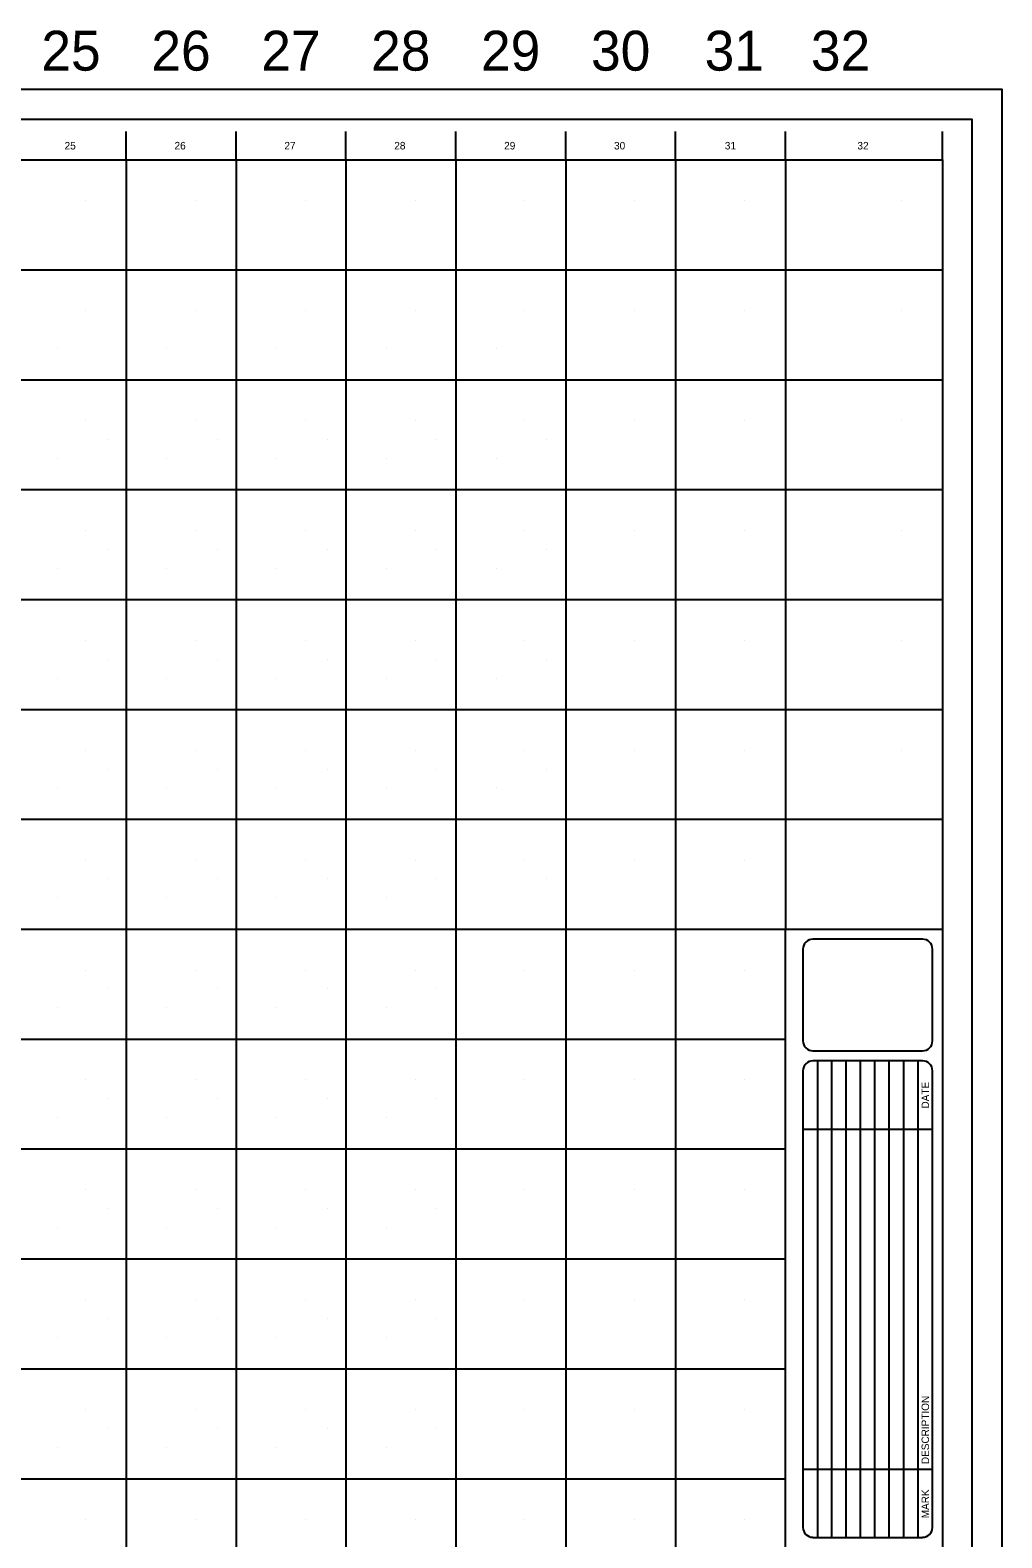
# Model space of a CAD drawing. Extents: x -0.05 to 1.19, y 0 to 0.86.
# Drawn here: x 0.8795 to 1.189, y 0.3796 to 0.8598 of the extents above; entities that cross this region are included whole.
import ezdxf

# ---------------------------------------------------------------- set-up
doc = ezdxf.new("R2010")
doc.units = 0
for name, color, linetype in [('G-ANNO-NPLT', 7, 'Continuous'), ('G-ANNO-TEXT', 7, 'Continuous'), ('G-ANNO-TTLB', 7, 'Continuous'), ('G-ANNO-TTLB-GRID', 7, 'Continuous')]:
    doc.layers.add(name, color=color, linetype=linetype)

msp = doc.modelspace()

# ---------------------------------------------------------------- linework, layer by layer
at = {"layer": 'G-ANNO-NPLT'}
for p, q in [((0.89707, 0.80547), (0.89707, 0.80547)), ((0.93207, 0.80547), (0.93207, 0.80547)), ((0.96707, 0.80547), (0.96707, 0.80547)), ((1.00208, 0.80547), (1.00208, 0.80547)), ((1.03707, 0.80547), (1.03707, 0.80547)), ((1.07207, 0.80547), (1.07207, 0.80547)), ((1.10708, 0.80547), (1.10708, 0.80547)), ((1.15709, 0.80547), (1.15709, 0.80547)), ((0.89707, 0.77047), (0.89707, 0.77047)), ((0.93207, 0.77047), (0.93207, 0.77047)), ((0.96707, 0.77047), (0.96707, 0.77047)), ((1.00208, 0.77047), (1.00208, 0.77047)), ((1.03707, 0.77047), (1.03707, 0.77047)), ((1.07207, 0.77047), (1.07207, 0.77047)), ((1.10708, 0.77047), (1.10708, 0.77047)), ((1.15709, 0.77047), (1.15709, 0.77047)), ((0.88807, 0.75847), (0.88807, 0.75847)), ((0.92307, 0.75847), (0.92307, 0.75847)), ((0.95808, 0.75847), (0.95808, 0.75847)), ((0.99307, 0.75847), (0.99307, 0.75847)), ((1.02807, 0.75847), (1.02807, 0.75847)), ((0.89707, 0.73547), (0.89707, 0.73547)), ((0.93207, 0.73547), (0.93207, 0.73547)), ((0.96707, 0.73547), (0.96707, 0.73547)), ((1.00208, 0.73547), (1.00208, 0.73547)), ((1.03707, 0.73547), (1.03707, 0.73547)), ((1.07207, 0.73547), (1.07207, 0.73547)), ((1.10708, 0.73547), (1.10708, 0.73547)), ((1.15709, 0.73547), (1.15709, 0.73547)), ((0.90407, 0.72947), (0.90407, 0.72947)), ((0.93907, 0.72947), (0.93907, 0.72947)), ((0.97407, 0.72947), (0.97407, 0.72947)), ((1.00907, 0.72947), (1.00907, 0.72947)), ((1.04408, 0.72947), (1.04408, 0.72947)), ((0.88807, 0.72347), (0.88807, 0.72347)), ((0.92307, 0.72347), (0.92307, 0.72347)), ((0.95808, 0.72347), (0.95808, 0.72347)), ((0.99307, 0.72347), (0.99307, 0.72347)), ((1.02807, 0.72347), (1.02807, 0.72347)), ((0.89707, 0.70047), (0.89707, 0.70047)), ((0.93207, 0.70047), (0.93207, 0.70047)), ((0.96707, 0.70047), (0.96707, 0.70047)), ((1.00208, 0.70047), (1.00208, 0.70047)), ((1.03707, 0.70047), (1.03707, 0.70047)), ((1.07207, 0.70047), (1.07207, 0.70047)), ((1.10708, 0.70047), (1.10708, 0.70047)), ((1.15709, 0.70047), (1.15709, 0.70047)), ((0.90407, 0.69447), (0.90407, 0.69447)), ((0.93907, 0.69447), (0.93907, 0.69447)), ((0.97407, 0.69447), (0.97407, 0.69447)), ((1.00907, 0.69447), (1.00907, 0.69447)), ((1.04408, 0.69447), (1.04408, 0.69447)), ((0.88807, 0.68847), (0.88807, 0.68847)), ((0.92307, 0.68847), (0.92307, 0.68847)), ((0.95808, 0.68847), (0.95808, 0.68847)), ((0.99307, 0.68847), (0.99307, 0.68847)), ((1.02807, 0.68847), (1.02807, 0.68847)), ((0.89707, 0.66547), (0.89707, 0.66547)), ((0.93207, 0.66547), (0.93207, 0.66547)), ((0.96707, 0.66547), (0.96707, 0.66547)), ((1.00208, 0.66547), (1.00208, 0.66547)), ((1.03707, 0.66547), (1.03707, 0.66547)), ((1.07207, 0.66547), (1.07207, 0.66547)), ((1.10708, 0.66547), (1.10708, 0.66547)), ((1.15709, 0.66547), (1.15709, 0.66547)), ((0.90407, 0.65947), (0.90407, 0.65947)), ((0.93907, 0.65947), (0.93907, 0.65947)), ((0.97407, 0.65947), (0.97407, 0.65947)), ((1.00907, 0.65947), (1.00907, 0.65947)), ((1.04408, 0.65947), (1.04408, 0.65947)), ((0.88807, 0.65347), (0.88807, 0.65347)), ((0.92307, 0.65347), (0.92307, 0.65347)), ((0.95808, 0.65347), (0.95808, 0.65347)), ((0.99307, 0.65347), (0.99307, 0.65347)), ((1.02807, 0.65347), (1.02807, 0.65347)), ((0.89707, 0.63047), (0.89707, 0.63047)), ((0.93207, 0.63047), (0.93207, 0.63047)), ((0.96707, 0.63047), (0.96707, 0.63047)), ((1.00208, 0.63047), (1.00208, 0.63047)), ((1.03707, 0.63047), (1.03707, 0.63047)), ((1.07207, 0.63047), (1.07207, 0.63047)), ((1.10708, 0.63047), (1.10708, 0.63047)), ((1.15709, 0.63047), (1.15709, 0.63047)), ((0.90407, 0.62447), (0.90407, 0.62447)), ((0.93907, 0.62447), (0.93907, 0.62447)), ((0.97407, 0.62447), (0.97407, 0.62447)), ((1.00907, 0.62447), (1.00907, 0.62447)), ((1.04408, 0.62447), (1.04408, 0.62447)), ((0.88807, 0.61847), (0.88807, 0.61847)), ((0.92307, 0.61847), (0.92307, 0.61847)), ((0.95808, 0.61847), (0.95808, 0.61847)), ((0.99307, 0.61847), (0.99307, 0.61847)), ((1.02807, 0.61847), (1.02807, 0.61847)), ((0.89707, 0.59547), (0.89707, 0.59547)), ((0.93207, 0.59547), (0.93207, 0.59547)), ((0.96707, 0.59547), (0.96707, 0.59547)), ((1.00208, 0.59547), (1.00208, 0.59547)), ((1.03707, 0.59547), (1.03707, 0.59547)), ((1.07207, 0.59547), (1.07207, 0.59547)), ((1.10708, 0.59547), (1.10708, 0.59547)), ((0.90407, 0.58947), (0.90407, 0.58947)), ((0.93907, 0.58947), (0.93907, 0.58947)), ((0.97407, 0.58947), (0.97407, 0.58947)), ((1.00907, 0.58947), (1.00907, 0.58947)), ((1.04408, 0.58947), (1.04408, 0.58947)), ((0.88807, 0.58347), (0.88807, 0.58347)), ((0.92307, 0.58347), (0.92307, 0.58347)), ((0.95808, 0.58347), (0.95808, 0.58347)), ((0.99307, 0.58347), (0.99307, 0.58347)), ((0.89707, 0.56047), (0.89707, 0.56047)), ((0.93207, 0.56047), (0.93207, 0.56047)), ((0.96707, 0.56047), (0.96707, 0.56047)), ((1.00208, 0.56047), (1.00208, 0.56047)), ((1.03707, 0.56047), (1.03707, 0.56047)), ((1.07207, 0.56047), (1.07207, 0.56047)), ((1.10708, 0.56047), (1.10708, 0.56047)), ((0.90407, 0.55447), (0.90407, 0.55447)), ((0.93907, 0.55447), (0.93907, 0.55447)), ((0.97407, 0.55447), (0.97407, 0.55447)), ((1.00907, 0.55447), (1.00907, 0.55447)), ((0.88807, 0.54847), (0.88807, 0.54847)), ((0.92307, 0.54847), (0.92307, 0.54847)), ((0.95808, 0.54847), (0.95808, 0.54847)), ((0.99307, 0.54847), (0.99307, 0.54847)), ((0.89707, 0.52547), (0.89707, 0.52547)), ((0.93207, 0.52547), (0.93207, 0.52547)), ((0.96707, 0.52547), (0.96707, 0.52547)), ((1.00208, 0.52547), (1.00208, 0.52547)), ((1.03707, 0.52547), (1.03707, 0.52547)), ((1.07207, 0.52547), (1.07207, 0.52547)), ((1.10708, 0.52547), (1.10708, 0.52547)), ((0.90407, 0.51947), (0.90407, 0.51947)), ((0.93907, 0.51947), (0.93907, 0.51947)), ((0.97407, 0.51947), (0.97407, 0.51947)), ((1.00907, 0.51947), (1.00907, 0.51947)), ((0.88807, 0.51347), (0.88807, 0.51347)), ((0.92307, 0.51347), (0.92307, 0.51347)), ((0.95808, 0.51347), (0.95808, 0.51347)), ((0.99307, 0.51347), (0.99307, 0.51347)), ((0.89707, 0.49047), (0.89707, 0.49047)), ((0.93207, 0.49047), (0.93207, 0.49047)), ((0.96707, 0.49047), (0.96707, 0.49047)), ((1.00208, 0.49047), (1.00208, 0.49047)), ((1.03707, 0.49047), (1.03707, 0.49047)), ((1.07207, 0.49047), (1.07207, 0.49047)), ((1.10708, 0.49047), (1.10708, 0.49047)), ((0.90407, 0.48447), (0.90407, 0.48447)), ((0.93907, 0.48447), (0.93907, 0.48447)), ((0.97407, 0.48447), (0.97407, 0.48447)), ((1.00907, 0.48447), (1.00907, 0.48447)), ((0.88807, 0.47847), (0.88807, 0.47847)), ((0.92307, 0.47847), (0.92307, 0.47847)), ((0.95808, 0.47847), (0.95808, 0.47847)), ((0.99307, 0.47847), (0.99307, 0.47847)), ((0.89707, 0.45547), (0.89707, 0.45547)), ((0.93207, 0.45547), (0.93207, 0.45547)), ((0.96707, 0.45547), (0.96707, 0.45547)), ((1.00208, 0.45547), (1.00208, 0.45547)), ((1.03707, 0.45547), (1.03707, 0.45547)), ((1.07207, 0.45547), (1.07207, 0.45547)), ((1.10708, 0.45547), (1.10708, 0.45547)), ((0.90407, 0.44947), (0.90407, 0.44947)), ((0.93907, 0.44947), (0.93907, 0.44947)), ((0.97407, 0.44947), (0.97407, 0.44947)), ((1.00907, 0.44947), (1.00907, 0.44947)), ((0.88807, 0.44347), (0.88807, 0.44347)), ((0.92307, 0.44347), (0.92307, 0.44347)), ((0.95808, 0.44347), (0.95808, 0.44347)), ((0.99307, 0.44347), (0.99307, 0.44347)), ((0.89707, 0.42047), (0.89707, 0.42047)), ((0.93207, 0.42047), (0.93207, 0.42047)), ((0.96707, 0.42047), (0.96707, 0.42047)), ((1.00208, 0.42047), (1.00208, 0.42047)), ((1.03707, 0.42047), (1.03707, 0.42047)), ((1.07207, 0.42047), (1.07207, 0.42047)), ((1.10708, 0.42047), (1.10708, 0.42047)), ((0.90407, 0.41447), (0.90407, 0.41447)), ((0.93907, 0.41447), (0.93907, 0.41447)), ((0.97407, 0.41447), (0.97407, 0.41447)), ((1.00907, 0.41447), (1.00907, 0.41447)), ((0.88807, 0.40847), (0.88807, 0.40847)), ((0.92307, 0.40847), (0.92307, 0.40847)), ((0.95808, 0.40847), (0.95808, 0.40847)), ((0.99307, 0.40847), (0.99307, 0.40847)), ((0.89707, 0.38547), (0.89707, 0.38547)), ((0.93207, 0.38547), (0.93207, 0.38547)), ((0.96707, 0.38547), (0.96707, 0.38547)), ((1.00208, 0.38547), (1.00208, 0.38547)), ((1.03707, 0.38547), (1.03707, 0.38547)), ((1.07207, 0.38547), (1.07207, 0.38547)), ((1.10708, 0.38547), (1.10708, 0.38547))]:
    msp.add_line(p, q, dxfattribs=at)
msp.add_lwpolyline([(0.00952, 0.83147), (1.17948, 0.83147), (1.17948, 0.00952), (0.00952, 0.00952)], close=True, dxfattribs=at)
at = {"layer": 'G-ANNO-TEXT'}
for p, q in [((0.91007, 0.81847), (0.91007, 0.82753)), ((0.94507, 0.81847), (0.94507, 0.82753)), ((0.98007, 0.81847), (0.98007, 0.82753)), ((1.01507, 0.81847), (1.01507, 0.82753)), ((1.05007, 0.81847), (1.05007, 0.82753)), ((1.08508, 0.81847), (1.08508, 0.82753)), ((1.12007, 0.81847), (1.12007, 0.82753)), ((1.17009, 0.81847), (1.17009, 0.82753))]:
    msp.add_line(p, q, dxfattribs=at)
at = {"layer": 'G-ANNO-TTLB'}
for p, q in [((1.13023, 0.53156), (1.13023, 0.37979)), ((1.13481, 0.37979), (1.13481, 0.53156)), ((1.1394, 0.37979), (1.1394, 0.53156)), ((1.14399, 0.37979), (1.14399, 0.53156)), ((1.14857, 0.37979), (1.14857, 0.53156)), ((1.15316, 0.37979), (1.15316, 0.53156)), ((1.15775, 0.37979), (1.15775, 0.53156)), ((1.16233, 0.37979), (1.16233, 0.53156)), ((1.12565, 0.50983), (1.16692, 0.50983)), ((1.12565, 0.40153), (1.16692, 0.40153))]:
    msp.add_line(p, q, dxfattribs=at)
for points in [[(0, 0.841), (1.189, 0.841), (1.189, 0), (0, 0)], [(0.03507, 0.81847), (1.17009, 0.81847), (1.17009, 0.01347), (0.03507, 0.01347)], [(1.12007, 0.57347), (1.17009, 0.57347), (1.17009, 0.01347), (1.12007, 0.01347)]]:
    msp.add_lwpolyline(points, close=True, dxfattribs=at)
for points in [[(1.12565, 0.56712), (1.12565, 0.53791)], [(1.16374, 0.57029), (1.12882, 0.57029)], [(1.16692, 0.53791), (1.16692, 0.56712)], [(1.12882, 0.53473), (1.16374, 0.53473)], [(1.12565, 0.52838), (1.12565, 0.38297)], [(1.16374, 0.53156), (1.12882, 0.53156)], [(1.16692, 0.38297), (1.16692, 0.52838)], [(1.12882, 0.37979), (1.16374, 0.37979)]]:
    msp.add_lwpolyline(points, dxfattribs=at)
for centre, start, end in [((1.12882, 0.56712), 90, 180), ((1.16374, 0.56712), 0, 90), ((1.12882, 0.53791), 180, 270), ((1.16374, 0.53791), 270, 0), ((1.12882, 0.52838), 90, 180), ((1.16374, 0.52838), 0, 90), ((1.12882, 0.38297), 180, 270), ((1.16374, 0.38297), 270, 0)]:
    msp.add_arc(centre, 0.00317, start, end, dxfattribs=at)
at = {"layer": 'G-ANNO-TTLB-GRID'}
for p, q in [((0.91007, 0.81847), (0.91007, 0.01347)), ((0.94507, 0.81847), (0.94507, 0.01347)), ((0.98007, 0.81847), (0.98007, 0.01347)), ((1.01507, 0.81847), (1.01507, 0.01347)), ((1.05007, 0.81847), (1.05007, 0.01347)), ((1.08508, 0.81847), (1.08508, 0.01347)), ((1.12007, 0.81847), (1.12007, 0.57347)), ((0.03507, 0.78347), (1.17009, 0.78347)), ((0.03507, 0.74847), (1.17009, 0.74847)), ((0.03507, 0.71347), (1.17009, 0.71347)), ((0.03507, 0.67847), (1.17009, 0.67847)), ((0.03507, 0.64347), (1.17009, 0.64347)), ((0.03507, 0.60847), (1.17009, 0.60847)), ((0.03507, 0.57347), (1.12007, 0.57347)), ((0.03507, 0.53847), (1.12007, 0.53847)), ((0.03507, 0.50347), (1.12007, 0.50347)), ((0.03507, 0.46847), (1.12007, 0.46847)), ((0.03507, 0.43347), (1.12007, 0.43347)), ((0.03507, 0.39847), (1.12007, 0.39847))]:
    msp.add_line(p, q, dxfattribs=at)

# ---------------------------------------------------------------- texts
at = {"layer": 'G-ANNO-NPLT'}
for s, p in [('25', (0.88306, 0.8469)), ('26', (0.91811, 0.8469)), ('27', (0.95311, 0.8469)), ('28', (0.9881, 0.8469)), ('29', (1.0231, 0.8469)), ('30', (1.05814, 0.8469)), ('31', (1.09434, 0.8469)), ('32', (1.12818, 0.8469))]:
    msp.add_text(s, height=0.0127, dxfattribs=at).set_placement(p)
at = {"layer": 'G-ANNO-TEXT'}
for s, p in [('25', (0.89046, 0.8218)), ('26', (0.92547, 0.8218)), ('27', (0.96047, 0.8218)), ('28', (0.99547, 0.8218)), ('29', (1.03047, 0.8218)), ('30', (1.06547, 0.8218)), ('31', (1.10076, 0.8218)), ('32', (1.14299, 0.8218))]:
    msp.add_text(s, height=0.0024, dxfattribs=at).set_placement(p)
for s, height, p in [('DATE', 0.002381, (1.16581, 0.51635)), ('DESCRIPTION', 0.0023813, (1.16581, 0.40311)), ('MARK', 0.002381, (1.16581, 0.38586))]:
    msp.add_text(s, height=height, rotation=90, dxfattribs=at).set_placement(p)

doc.saveas('drawing.dxf')
